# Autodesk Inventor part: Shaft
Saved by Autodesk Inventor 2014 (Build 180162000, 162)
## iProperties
Created: 2010-12
Part Number: Shaft
Material: Steel
Document SubType Name: Modeling
Designer: Thom Tremblay
Density: 1 g/cm^3
Appearance: Steel
CustomPartVersion: 1
Author: Thom Tremblay
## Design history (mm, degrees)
sketch "Main Sketch"
  geometry: L1 (0, 0)-(51, 0) reference; L2 (0, 0)-(0, 5); L3 (26, 6)-(26, 12.5); L4 (0, 5)-(10, 5); L5 (41, 6)-(41, 5); L6 (38, 6)-(41, 6); L7 (51, 5)-(51, 0); L8 (41, 5)-(51, 5); L9 (38, 12.5)-(38, 6); L10 (26, 12.5)-(38, 12.5); L11 (10, 5)-(10, 6); L12 (10, 6)-(26, 6)
  constraints: 24 end point, 6 vertical, 2 horizontal
  dimensions: "d3" = 10 diameter of L4 L1 (derived); "d4" = 12 diameter of L6 L1 (derived); "d5" = 10 diameter of L8 L1 (derived); "d13" = 25 diameter of L10 L1 (derived); "d14" = 12 diameter of L12 L1 (derived)
revolve "Revolution1" sketch "Main Sketch" stored, may be unused: angle "d6" = 0 deg
chamfer "Chamfer4" distance "d18" = 0.5; stored, may be unused: second distance "d19" = 0.125, angle "d20" = 45 deg
chamfer "Chamfer2" distance "d10" = 0.5; stored, may be unused: second distance "d11" = 0.125, angle "d12" = 45 deg
node "Spur Gear Teeth1"
node "Keyway1"
body "Solid1"
feature "Spur Gear1"
feature "Shaft Keyway"
other parameters: "d0" = 0, "d1" = 0, "d2" = 0
